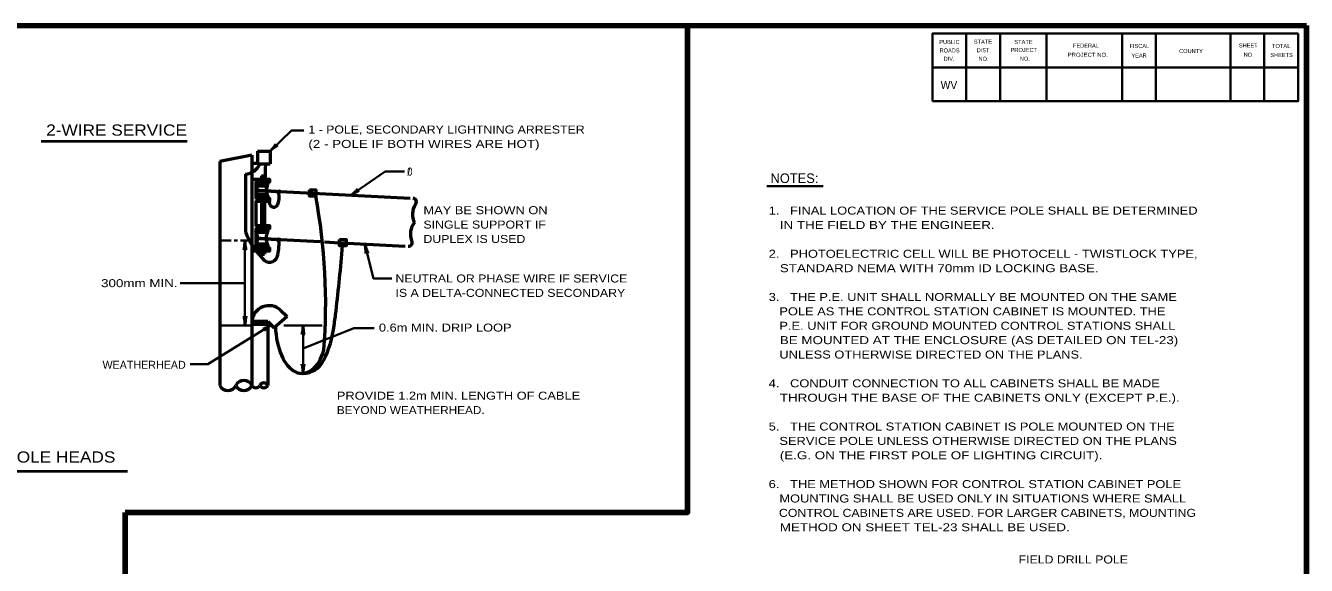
# Model space of a CAD drawing. Extents: x -33 to 680, y -7 to 447.
# Drawn here: x 274.7 to 674.8, y 272.6 to 441.4 of the extents above; entities that cross this region are included whole.
import ezdxf

# ---------------------------------------------------------------- set-up
doc = ezdxf.new("R2010")
doc.units = 0
doc.layers.add('1', color=7, linetype='Continuous', lineweight=53)
doc.layers.add('61', color=7, linetype='Continuous', lineweight=35)

msp = doc.modelspace()

# ---------------------------------------------------------------- hatches: boundary and pattern name
at = {"layer": '1'}
for points in [[(354.331, 389.564, 1), (353.331, 389.564, 1)], [(354.301, 374.562, 1), (353.301, 374.562, 1)]]:
    msp.add_hatch(color=256, dxfattribs=at).paths.add_polyline_path(points)

# ---------------------------------------------------------------- linework, layer by layer
at = {"layer": '1', "lineweight": 158}
msp.add_line((674.767, 2.994), (674.767, 441.411), dxfattribs=at)
at = {"layer": '1', "lineweight": 13}
msp.add_line((674.767, 2.994), (674.767, 441.411), dxfattribs=at)
at = {"layer": '1', "lineweight": 40}
for p, q in [((279.553, 405.318), (325.098, 405.318)), ((216.934, 302.073), (306.519, 302.073))]:
    msp.add_line(p, q, dxfattribs=at)
at = {"layer": '1'}
for p, q in [((345.342, 400.924), (335.342, 398.924)), ((345.342, 400.924), (345.342, 328.924)), ((347.092, 402.174), (347.092, 398.174)), ((347.092, 402.174), (351.092, 402.174)), ((351.092, 402.174), (351.092, 398.174)), ((335.342, 398.924), (335.342, 328.924)), ((345.342, 398.424), (347.092, 398.424)), ((347.092, 398.174), (351.092, 398.174)), ((343.342, 394.924), (343.342, 376.924)), ((348.342, 394.424), (349.342, 394.424)), ((348.342, 394.424), (348.342, 393.424)), ((349.342, 394.424), (349.342, 393.424)), ((350.342, 391.674), (350.342, 392.424)), ((350.342, 391.674), (346.592, 391.674)), ((346.592, 388.174), (350.342, 388.174)), ((350.121, 391.174), (346.813, 391.174)), ((346.813, 388.674), (350.121, 388.674)), ((350.342, 388.174), (350.342, 387.424)), ((354.331, 389.569), (394.773, 387.45)), ((348.342, 386.424), (348.342, 378.924)), ((349.342, 386.424), (349.342, 378.924)), ((350.342, 377.174), (346.592, 377.174)), ((350.104, 376.674), (346.829, 376.674)), ((350.342, 377.174), (350.342, 377.924)), ((346.592, 372.674), (350.342, 372.674)), ((346.829, 373.174), (350.104, 373.174)), ((350.342, 372.674), (350.342, 371.924)), ((354.299, 374.518), (366.645, 373.871)), ((348.342, 370.924), (348.342, 369.924)), ((348.342, 369.924), (349.342, 369.924)), ((349.342, 370.924), (349.342, 369.924)), ((354.342, 352.424), (356.342, 350.424)), ((350.342, 348.924), (345.342, 348.924)), ((350.342, 348.924), (350.342, 328.924)), ((350.342, 348.924), (352.342, 346.924)), ((356.342, 350.424), (352.342, 346.924)), ((350.342, 347.924), (345.342, 347.924))]:
    msp.add_line(p, q, dxfattribs=at)
at = {"layer": '1', "lineweight": 35}
for p, q in [((506.239, 391.237), (523.847, 391.237)), ((338.842, 374.174), (335.842, 374.174)), ((340.842, 374.174), (339.842, 374.174)), ((344.842, 374.174), (341.842, 374.174)), ((343.195, 347.674), (343.195, 374.174)), ((343.195, 360.924), (322.946, 360.924)), ((344.842, 347.674), (335.842, 347.674)), ((355.342, 347.674), (367.342, 347.674)), ((361.342, 332.674), (361.342, 347.674))]:
    msp.add_line(p, q, dxfattribs=at)
at = {"layer": '1', "lineweight": 106}
msp.add_line((305.763, 289.208), (305.763, 2.994), dxfattribs=at)
at = {"layer": '1', "lineweight": 158}
msp.add_lwpolyline([(674.767, 441.411), (15.017, 441.328), (15.1, 2.994)], dxfattribs=at)
at = {"layer": '1', "lineweight": 106}
msp.add_lwpolyline([(305.763, 289.208), (481.467, 289.208), (481.467, 441.387)], dxfattribs=at)
at = {"layer": '1', "lineweight": 35}
for points in [[(351.092, 402.174), (357.701, 408.599), (361.591, 408.617)], [(376.292, 388.418), (387.003, 395.805), (393.04, 395.805)], [(380.64, 373.037), (383.332, 362.347), (389.043, 362.347)], [(351.438, 347.883), (331.605, 335.534), (326.106, 335.534)], [(361.326, 340.45), (377.239, 346.771), (383.558, 346.771)]]:
    msp.add_lwpolyline(points, dxfattribs=at)
at = {"layer": '1'}
for points in [[(345.342, 393.424), (350.842, 393.424), (350.842, 392.424), (346.592, 392.424), (346.592, 387.424), (350.842, 387.424), (350.842, 386.424), (346.592, 386.424), (346.592, 378.924), (350.842, 378.924), (350.842, 377.924), (346.592, 377.924), (346.592, 371.924), (350.842, 371.924), (350.842, 370.924), (345.342, 370.924)], [(346.779, 389.924), (346.868, 389.917), (346.936, 389.917), (347.005, 389.909), (347.05, 389.909), (347.103, 389.909), (347.156, 389.909), (347.217, 389.917), (347.338, 389.94), (347.361, 389.932), (347.399, 389.917), (347.437, 389.924), (347.46, 389.917), (347.581, 389.917), (347.649, 389.856), (347.642, 389.849), (347.672, 389.871), (347.733, 389.849), (347.793, 389.849), (347.854, 389.879), (347.862, 389.887), (347.922, 389.902), (347.953, 389.887), (347.991, 389.864), (348.021, 389.856), (348.173, 389.841), (348.226, 389.856), (348.332, 389.834), (348.362, 389.864), (348.423, 389.864), (348.537, 389.826), (348.552, 389.826), (348.605, 389.826), (348.832, 389.849), (348.84, 389.849), (348.893, 389.834), (349.022, 389.811), (349.143, 389.818), (349.234, 389.818), (349.318, 389.826), (349.394, 389.834), (349.454, 389.803), (349.568, 389.796), (349.591, 389.75), (349.674, 389.742), (349.818, 389.735), (349.856, 389.75), (349.947, 389.78), (350.069, 389.803), (350.145, 389.765), (350.152, 389.765), (350.175, 389.72), (350.395, 389.773), (350.418, 389.75), (350.448, 389.742), (350.577, 389.742), (350.6, 389.735), (350.706, 389.758), (350.751, 389.75), (350.82, 389.735), (350.858, 389.75), (350.941, 389.742), (351.04, 389.75), (351.153, 389.742), (351.214, 389.712), (351.252, 389.674), (351.26, 389.667), (351.388, 389.682), (351.442, 389.674), (351.563, 389.674), (351.616, 389.659), (351.715, 389.667), (351.98, 389.667), (352.018, 389.667), (352.086, 389.674), (352.177, 389.667), (352.215, 389.644), (352.291, 389.636), (352.412, 389.606), (352.526, 389.629), (352.572, 389.636), (352.685, 389.629), (352.769, 389.613), (352.799, 389.575), (352.898, 389.583), (353.042, 389.583), (353.148, 389.575), (353.194, 389.598), (353.3, 389.591), (353.376, 389.613)], [(346.92, 374.924), (347.009, 374.917), (347.077, 374.917), (347.145, 374.909), (347.191, 374.909), (347.244, 374.909), (347.297, 374.909), (347.358, 374.917), (347.479, 374.94), (347.502, 374.932), (347.54, 374.917), (347.578, 374.924), (347.601, 374.917), (347.722, 374.917), (347.79, 374.856), (347.783, 374.849), (347.813, 374.871), (347.874, 374.849), (347.934, 374.849), (347.995, 374.879), (348.002, 374.887), (348.063, 374.902), (348.094, 374.887), (348.131, 374.864), (348.162, 374.856), (348.313, 374.841), (348.367, 374.856), (348.473, 374.834), (348.503, 374.864), (348.564, 374.864), (348.678, 374.826), (348.693, 374.826), (348.746, 374.826), (348.973, 374.849), (348.981, 374.849), (349.034, 374.834), (349.163, 374.811), (349.284, 374.818), (349.375, 374.818), (349.459, 374.826), (349.535, 374.834), (349.595, 374.803), (349.709, 374.796), (349.732, 374.75), (349.815, 374.742), (349.959, 374.735), (349.997, 374.75), (350.088, 374.78), (350.21, 374.803), (350.286, 374.765), (350.293, 374.765), (350.316, 374.72), (350.536, 374.773), (350.558, 374.75), (350.589, 374.742), (350.718, 374.742), (350.741, 374.735), (350.847, 374.758), (350.892, 374.75), (350.96, 374.735), (350.998, 374.75), (351.082, 374.742), (351.18, 374.75), (351.294, 374.742), (351.355, 374.712), (351.393, 374.674), (351.4, 374.667), (351.529, 374.682), (351.582, 374.674), (351.704, 374.674), (351.757, 374.659), (351.856, 374.667), (352.121, 374.667), (352.159, 374.667), (352.227, 374.674), (352.318, 374.667), (352.356, 374.644), (352.432, 374.636), (352.553, 374.606), (352.667, 374.629), (352.713, 374.636), (352.826, 374.629), (352.91, 374.613), (352.94, 374.575), (353.039, 374.583), (353.183, 374.583), (353.289, 374.575), (353.334, 374.598), (353.441, 374.591), (353.517, 374.613)], [(367.994, 373.801), (371.154, 373.635), (393.249, 372.477)]]:
    msp.add_lwpolyline(points, dxfattribs=at)
for points in [[(363.319, 390.098), (365.319, 390.098), (365.319, 388.098), (363.319, 388.098)], [(372.774, 374.55), (374.774, 374.55), (374.774, 372.55), (372.774, 372.55)]]:
    msp.add_lwpolyline(points, close=True, dxfattribs=at)
at = {"layer": '1', "lineweight": 13}
for centre in [(353.831, 389.564), (353.801, 374.562)]:
    msp.add_circle(centre, 0.5, dxfattribs=at)
at = {"layer": '1'}
for centre, radius, start, end in [((342.831, 400.371), 5.471, 275.35282, 336.32248), ((382.272, 395.308), 32.806, 174.98859, 197.57614), ((343.309, 389.924), 3.72, 331.93494, 28.06506), ((353.624, 389.924), 3.72, 151.93494, 208.06506), ((346.504, 388.037), 7.39, 338.28432, 8.16262), ((181.504, 354.235), 186.908, 355.61418, 10.4382), ((352.211, 386.025), 1.364, 207.17977, 328.05521), ((401.123, 382.388), 5.621, 146.88569, 207.1631), ((395.611, 386.278), 1.147, 314.46081, 81.61314), ((364.838, 384.911), 22.932, 200.38305, 225.6141), ((342.503, 374.924), 4.667, 331.17388, 28.82612), ((354.43, 374.924), 4.667, 151.17388, 208.82612), ((400.48, 376.272), 5.621, 140.8369, 201.11431), ((339.376, 373.165), 14.472, 343.68787, 3.62999), ((-513.562, 452.114), 890.834, 353.55933, 354.87476), ((394.28, 373.613), 1.147, 266.38686, 33.53919), ((350.875, 370.022), 2.562, 215.81165, 338.90815), ((350.703, 348.459), 5.382, 47.45902, 175.04199), ((275.516, 363.118), 96.753, 350.82752, 353.51226), ((339.279, 351.188), 31.945, 332.97577, 353.72112), ((361.216, 339.985), 7.312, 270.98195, 333.07352), ((337.842, 330.116), 2.77, 205.49727, 334.50273), ((342.842, 327.732), 2.77, 25.49727, 154.50273), ((342.842, 330.116), 2.77, 205.49727, 334.50273), ((346.592, 329.58), 1.412, 207.68943, 332.31057), ((349.092, 328.268), 1.412, 27.68943, 152.31057), ((349.092, 329.58), 1.412, 207.68943, 332.31057)]:
    msp.add_arc(centre, radius, start, end, dxfattribs=at)
at = {"layer": '1', "lineweight": 40}
for centre, major_axis, ratio, start_param, end_param in [((351.681, 403.133), (-1.172, -1.357), 0.122415, 0.8963533, 3.1415927), ((352.043, 402.803), (1.382, 1.098), 0.07063, 6.2823074, 8.5597026), ((377.034, 389.265), (-1.381, -1.142), 0.122415, 0.8963533, 3.1415927), ((377.034, 389.265), (-1.381, -1.142), 0.122415, 0.8963533, 3.1415927), ((377.335, 388.88), (1.546, 0.853), 0.07063, 6.2823074, 8.5597026), ((377.335, 388.88), (1.546, 0.853), 0.07063, 6.2823074, 8.5597026), ((342.984, 373.053), (0.176, 1.756), 0.07063, 3.1407148, 5.41811), ((342.984, 373.053), (0.176, 1.756), 0.07063, 3.1407148, 5.41811), ((343.472, 373.083), (-0.156, 1.786), 0.122415, 0.8963533, 3.1415927), ((343.472, 373.083), (-0.156, 1.786), 0.122415, 0.8963533, 3.1415927), ((380.709, 371.899), (-0.259, 1.746), 0.07063, 3.1407148, 5.41811), ((380.709, 371.899), (-0.259, 1.746), 0.07063, 3.1407148, 5.41811), ((381.175, 372.046), (-0.587, 1.694), 0.122415, 0.8963533, 3.1415927), ((381.175, 372.046), (-0.587, 1.694), 0.122415, 0.8963533, 3.1415927), ((342.919, 348.765), (0.156, -1.786), 0.122415, 0.8963533, 3.1415927), ((343.407, 348.794), (-0.176, -1.756), 0.07063, 3.1407148, 5.41811), ((350.375, 347.47), (-1.584, -0.779), 0.07063, 6.2823074, 8.5597026), ((350.658, 347.072), (1.433, 1.076), 0.122415, 0.8963533, 3.1415927), ((361.13, 346.553), (0.176, 1.756), 0.07063, 3.1407148, 5.41811), ((361.13, 346.553), (0.176, 1.756), 0.07063, 3.1407148, 5.41811), ((361.618, 346.583), (-0.156, 1.786), 0.122415, 0.8963533, 3.1415927), ((361.618, 346.583), (-0.156, 1.786), 0.122415, 0.8963533, 3.1415927), ((361.065, 333.765), (0.156, -1.786), 0.122415, 0.8963533, 3.1415927), ((361.065, 333.765), (0.156, -1.786), 0.122415, 0.8963533, 3.1415927), ((361.553, 333.794), (-0.176, -1.756), 0.07063, 3.1407148, 5.41811), ((361.553, 333.794), (-0.176, -1.756), 0.07063, 3.1407148, 5.41811)]:
    msp.add_ellipse(centre, major_axis=major_axis, ratio=ratio, start_param=start_param, end_param=end_param, dxfattribs=at)
at = {"layer": '1'}
msp.add_ellipse((360.78, 347.464), major_axis=(-0.386, 14.798), ratio=0.544805, start_param=1.5707963, end_param=4.1650301, dxfattribs=at)
at = {"layer": '61'}
for p, q in [((568.517, 438.911), (568.517, 417.744)), ((579.1, 438.911), (579.1, 417.744)), ((593.6, 438.911), (593.6, 417.744)), ((617.184, 438.911), (617.184, 417.744)), ((627.767, 438.911), (627.767, 417.744)), ((651.017, 438.911), (651.017, 417.744)), ((661.6, 438.911), (661.6, 417.744)), ((672.184, 428.328), (557.934, 428.328))]:
    msp.add_line(p, q, dxfattribs=at)
for points in [[(672.184, 438.911), (557.934, 438.911), (557.934, 417.744)], [(672.184, 438.911), (672.184, 417.744), (557.934, 417.744)]]:
    msp.add_lwpolyline(points, dxfattribs=at)

# ---------------------------------------------------------------- texts
at = {"layer": '1'}
for s, height, width, p in [('WV', 2.54, 0.95, (560.517, 421.578)), ('2-WIRE SERVICE', 3.5, 1.15, (281.106, 407)), ('1 - POLE, SECONDARY LIGHTNING ARRESTER', 2.5, 1.15, (363.005, 407.671)), ('(2 - POLE IF BOTH WIRES ARE HOT)', 2.5, 1.25, (363.005, 403.171)), ('0', 2.5, 0.9, (393.852, 394.512)), ('MAY BE SHOWN ON', 2.5, 1.2, (398.948, 382.454)), ('1.   FINAL LOCATION OF THE SERVICE POLE SHALL BE DETERMINED', 2.5, 1.2, (506.797, 382.322)), ('SINGLE SUPPORT IF', 2.5, 1.15, (398.948, 377.954)), ('   IN THE FIELD BY THE ENGINEER.', 2.5, 1.25, (506.797, 377.822)), ('DUPLEX IS USED', 2.5, 1.15, (398.948, 373.454)), ('2.   PHOTOELECTRIC CELL WILL BE PHOTOCELL - TWISTLOCK TYPE,', 2.5, 1.2, (506.797, 368.822)), ('   STANDARD NEMA WITH 70mm ID LOCKING BASE.', 2.5, 1.25, (506.797, 364.322)), ('300mm MIN.', 2.5, 1.25, (298.243, 359.637)), ('NEUTRAL OR PHASE WIRE IF SERVICE', 2.5, 1.15, (390.213, 361.101)), ('IS A DELTA-CONNECTED SECONDARY', 2.5, 1.15, (390.213, 356.601)), ('3.   THE P.E. UNIT SHALL NORMALLY BE MOUNTED ON THE SAME', 2.5, 1.2, (506.797, 355.322)), ('   POLE AS THE CONTROL STATION CABINET IS MOUNTED. THE', 2.5, 1.2, (506.797, 350.822)), ('0.6m MIN. DRIP LOOP', 2.5, 1.2, (385.025, 345.746)), ('   P.E. UNIT FOR GROUND MOUNTED CONTROL STATIONS SHALL', 2.5, 1.2, (506.797, 346.322)), ('   BE MOUNTED AT THE ENCLOSURE (AS DETAILED ON TEL-23)', 2.5, 1.25, (506.797, 341.822)), ('   UNLESS OTHERWISE DIRECTED ON THE PLANS.', 2.5, 1.2, (506.797, 337.322)), ('4.   CONDUIT CONNECTION TO ALL CABINETS SHALL BE MADE', 2.5, 1.2, (506.797, 328.322)), ('PROVIDE 1.2m MIN. LENGTH OF CABLE', 2.5, 1.2, (371.898, 324.463)), ('   THROUGH THE BASE OF THE CABINETS ONLY (EXCEPT P.E.).', 2.5, 1.25, (506.797, 323.822)), ('BEYOND WEATHERHEAD.', 2.5, 1.1, (371.898, 319.963)), ('5.   THE CONTROL STATION CABINET IS POLE MOUNTED ON THE', 2.5, 1.2, (506.797, 314.822)), ('   SERVICE POLE UNLESS OTHERWISE DIRECTED ON THE PLANS', 2.5, 1.2, (506.797, 310.322)), ('TYPICAL SERVICE POLE HEADS', 3.5, 1.15, (219.26, 304.788)), ('   (E.G. ON THE FIRST POLE OF LIGHTING CIRCUIT).', 2.5, 1.25, (506.797, 305.822)), ('6.   THE METHOD SHOWN FOR CONTROL STATION CABINET POLE', 2.5, 1.2, (506.797, 296.822)), ('   MOUNTING SHALL BE USED ONLY IN SITUATIONS WHERE SMALL', 2.5, 1.2, (506.797, 292.322)), ('   CONTROL CABINETS ARE USED. FOR LARGER CABINETS, MOUNTING', 2.5, 1.15, (506.797, 287.822)), ('   METHOD ON SHEET TEL-23 SHALL BE USED.', 2.5, 1.25, (506.797, 283.322)), ('FIELD DRILL POLE', 2.5, 1.15, (584.858, 273.249))]:
    msp.add_text(s, height=height, dxfattribs=dict(at, width=width)).set_placement(p)
for s, height, p in [('/', 2.5, (393.946, 394.496)), ('NOTES:', 3, (507.386, 392.194)), ('WEATHERHEAD', 2.5, (298.687, 334.106))]:
    msp.add_text(s, height=height, dxfattribs=at).set_placement(p)
at = {"layer": '61'}
for s, height, rotation, p in [('PUBLIC', 1.271, 0.033, (560.1, 435.661)), ('ROADS', 1.27, 0.124, (560.184, 432.994)), ('DIST.', 1.27, 0.056, (571.767, 433.078)), ('FEDERAL', 1.27, 0.007, (601.85, 434.494)), ('FISCAL', 1.271, 359.942, (619.517, 434.411)), ('YEAR', 1.27, 0.105, (620.1, 431.411)), ('COUNTY', 1.269, 0.069, (635.017, 432.828)), ('SHEET', 1.271, 0.059, (653.684, 434.578)), ('SHEETS', 1.269, 359.959, (663.517, 431.578)), ('DIV.', 1.27, 359.932, (561.434, 430.411))]:
    msp.add_text(s, height=height, rotation=rotation, dxfattribs=at).set_placement(p)
for s, height, rotation, width, p in [('STATE', 1.271, 0.059, 1.05, (570.85, 435.744)), ('STATE', 1.271, 0.059, 1.05, (583.517, 435.661)), ('PROJECT', 1.27, 359.908, 1.05, (582.35, 433.161)), ('PROJECT NO.', 1.27, 359.922, 1.1, (600.184, 431.661)), ('NO.', 1.27, 359.852, 0.9, (655.184, 431.661)), ('TOTAL', 1.27, 359.926, 1.05, (664.017, 434.411)), ('NO.', 1.27, 359.852, 0.9, (572.35, 430.411)), ('NO.', 1.271, 0.225, 0.9, (585.267, 430.411))]:
    msp.add_text(s, height=height, rotation=rotation, dxfattribs=dict(at, width=width)).set_placement(p)

doc.saveas('drawing.dxf')
